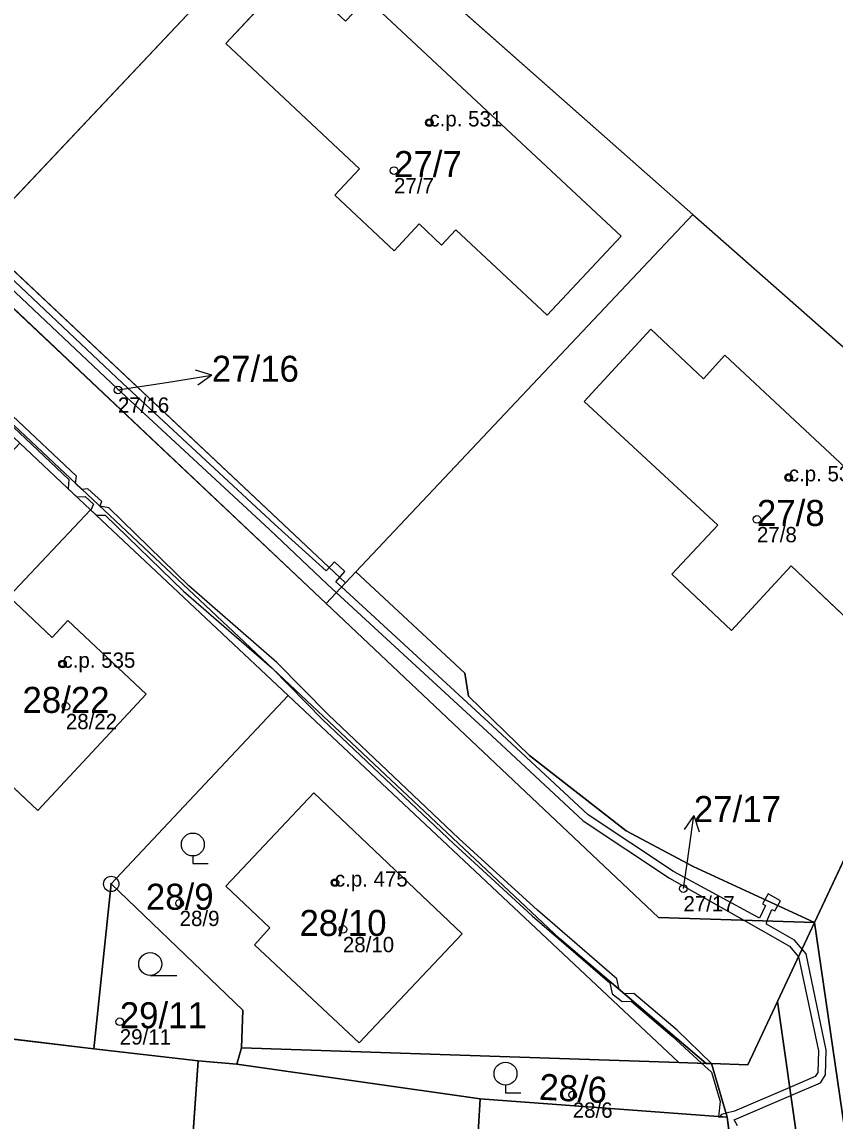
# Model space of a CAD drawing. Extents: x -603967 to -594699, y -1179315 to -1165625.
# Drawn here: x -597261.9 to -597208.8, y -1172594.2 to -1172522.4 of the extents above; entities that cross this region are included whole.
import ezdxf

# ---------------------------------------------------------------- set-up
doc = ezdxf.new("R2010")
doc.units = 0
for name, color, linetype in [('Definiční body', 7, 'Continuous'), ('Hranice parcel', 7, 'Continuous'), ('Parcelní čísla', 7, 'Continuous'), ('Polygon budovy', 7, 'Continuous'), ('Polygon parcely', 7, 'Continuous'), ('Pop  PČ popisy', 7, 'Continuous'), ('Vnitřní kresba', 7, 'Continuous'), ('Věcná břemena k části', 7, 'Continuous'), ('Značky bodu BP', 7, 'Continuous'), ('Značky budov', 7, 'Continuous'), ('Značky kultur', 7, 'Continuous')]:
    doc.layers.add(name, color=color, linetype=linetype)

msp = doc.modelspace()

# ---------------------------------------------------------------- linework, layer by layer
at = {"layer": 'Definiční body'}
for centre in [(-597235.25, -1172528.94994), (-597237.56, -1172532.07994), (-597255.59, -1172546.40994), (-597211.78, -1172552.12994), (-597213.86, -1172554.86994), (-597259.21, -1172564.30994), (-597258.99, -1172567.07994), (-597241.42, -1172578.59994), (-597218.66, -1172578.97994), (-597251.56, -1172579.93994), (-597240.9, -1172581.64994), (-597255.47, -1172587.67994), (-597225.89, -1172592.45994)]:
    msp.add_circle(centre, 0.25, dxfattribs=at)
at = {"layer": 'Hranice parcel'}
for p, q in [((-597242.77, -1172513.09), (-597264.76, -1172536.41)), ((-597242.77, -1172513.09), (-597218.04, -1172534.94)), ((-597218.04, -1172534.94), (-597240.05, -1172558.29)), ((-597218.04, -1172534.94), (-597197.09, -1172553.45)), ((-597264.76, -1172536.41), (-597240.72, -1172559)), ((-597265.99, -1172537.72), (-597242, -1172560.36)), ((-597197.09, -1172553.45), (-597210.1, -1172581.2)), ((-597240.72, -1172559), (-597240.05, -1172558.29)), ((-597242, -1172560.36), (-597240.72, -1172559)), ((-597244.48, -1172566.36), (-597256.03, -1172578.68)), ((-597218.97, -1172590.34), (-597244.48, -1172566.36)), ((-597257.17, -1172589.44), (-597256.03, -1172578.68)), ((-597212.52, -1172586.36), (-597210.1, -1172581.2)), ((-597206.62, -1172605.09), (-597210.1, -1172581.2)), ((-597212.52, -1172586.36), (-597214.45, -1172590.49)), ((-597200.46, -1172670.98), (-597212.52, -1172586.36)), ((-597257.17, -1172589.44), (-597265.61, -1172588.44)), ((-597250.35, -1172590.24), (-597257.17, -1172589.44)), ((-597247.51, -1172589.39), (-597247.83, -1172590.44)), ((-597218.97, -1172590.34), (-597247.51, -1172589.39)), ((-597251.5, -1172606.73), (-597250.35, -1172590.24)), ((-597247.83, -1172590.44), (-597250.35, -1172590.24)), ((-597247.83, -1172590.44), (-597231.93, -1172592.72)), ((-597218.97, -1172590.34), (-597217.17, -1172590.4)), ((-597217.17, -1172590.4), (-597216.82, -1172590.41)), ((-597214.45, -1172590.49), (-597216.82, -1172590.41)), ((-597216.82, -1172590.41), (-597215.81, -1172593.92)), ((-597215.81, -1172593.92), (-597231.93, -1172592.72)), ((-597212.67, -1172616.94), (-597215.81, -1172593.92))]:
    msp.add_line(p, q, dxfattribs=at)
for points in [[(-597217.17, -1172590.4), (-597226.76, -1172582.24), (-597272.66, -1172539.07), (-597331.22, -1172484)], [(-597262, -1172549.89), (-597257.38, -1172554.24), (-597244.48, -1172566.36)], [(-597240.05, -1172558.29), (-597232.94, -1172564.92), (-597232.69, -1172566.42), (-597228.72, -1172570.29), (-597222.41, -1172575.2), (-597218.02, -1172577.53), (-597210.1, -1172581.2)], [(-597242, -1172560.36), (-597220.28, -1172580.86), (-597210.1, -1172581.2)], [(-597242.8, -1172572.72), (-597233.1, -1172581.93), (-597239.84, -1172589.06), (-597246.68, -1172582.65), (-597245.66, -1172581.55), (-597248.54, -1172578.82), (-597242.8, -1172572.72)], [(-597256.03, -1172578.68), (-597247.44, -1172586.92), (-597247.51, -1172589.39)], [(-597231.93, -1172592.72), (-597232.16, -1172596.37), (-597233.65, -1172619.93)]]:
    msp.add_lwpolyline(points, dxfattribs=at)
at = {"layer": 'Polygon budovy'}
for points in [[(-597244.17, -1172519.1), (-597248.54, -1172523.78), (-597239.82, -1172531.97), (-597241.43, -1172533.68), (-597237.56, -1172537.33), (-597235.92, -1172535.57), (-597234.46, -1172536.95), (-597233.52, -1172535.95), (-597227.55, -1172541.53), (-597222.73, -1172536.37), (-597239.33, -1172520.84), (-597240.73, -1172522.32)], [(-597220.78, -1172542.45), (-597225.15, -1172547.16), (-597216.41, -1172555.25), (-597219.42, -1172558.44), (-597215.53, -1172562.12), (-597211.62, -1172557.91), (-597204.51, -1172564.65), (-597201.22, -1172557.91), (-597215.95, -1172544.14), (-597217.34, -1172545.68)], [(-597277.53, -1172566.42), (-597273.21, -1172570.48), (-597266.5, -1172563.37), (-597263.37, -1172566.3), (-597265.96, -1172569.05), (-597260.83, -1172573.88), (-597253.74, -1172566.29), (-597258.87, -1172561.48), (-597259.89, -1172562.57), (-597262.71, -1172559.91), (-597257.38, -1172554.24), (-597262, -1172549.89), (-597273.72, -1172562.36)], [(-597248.54, -1172578.82), (-597245.66, -1172581.55), (-597246.68, -1172582.65), (-597239.84, -1172589.06), (-597233.1, -1172581.93), (-597242.8, -1172572.72)]]:
    msp.add_lwpolyline(points, close=True, dxfattribs=at)
at = {"layer": 'Polygon parcely'}
for points in [[(-597230.58, -1172397.86), (-597225.66, -1172519.43), (-597370.04, -1172389.55), (-597371.62, -1172396.88), (-597322.85, -1172441.5), (-597295.24, -1172466.75), (-597267.51, -1172491.25), (-597242.77, -1172513.09), (-597218.04, -1172534.94), (-597197.09, -1172553.45), (-597129.63, -1172592.38), (-597127.98, -1172593.36), (-597111.9, -1172603.92), (-597081.9, -1172619.48), (-597063.74, -1172628.93), (-597028.61, -1172647.14), (-597018, -1172652.66), (-597016.16, -1172524.9), (-597116.51, -1172532.05), (-597117.85, -1172513.57), (-597182.62, -1172520.24), (-597187.57, -1172402.48), (-597194.03, -1172394.46), (-597229.74, -1172397.83)], [(-597327.23, -1172482.83), (-597329.2, -1172484.89), (-597330.78, -1172483.53), (-597331.22, -1172484), (-597272.66, -1172539.07), (-597226.76, -1172582.24), (-597217.17, -1172590.4), (-597216.82, -1172590.41), (-597214.45, -1172590.49), (-597212.52, -1172586.36), (-597210.1, -1172581.2), (-597220.28, -1172580.86), (-597242, -1172560.36), (-597265.99, -1172537.72), (-597289.98, -1172515.09), (-597314.07, -1172492.36), (-597314.89, -1172493.47)], [(-597262, -1172549.89), (-597257.38, -1172554.24), (-597244.48, -1172566.36), (-597218.97, -1172590.34), (-597217.17, -1172590.4), (-597226.76, -1172582.24), (-597272.66, -1172539.07), (-597331.22, -1172484), (-597331.65, -1172484.41), (-597305.83, -1172508.69), (-597295.83, -1172518.1), (-597291.22, -1172522.43), (-597286.6, -1172526.77), (-597276.61, -1172536.16), (-597266.62, -1172545.54)], [(-597264.76, -1172536.41), (-597242.77, -1172513.09), (-597267.51, -1172491.25), (-597288.81, -1172513.85)], [(-597240.05, -1172558.29), (-597218.04, -1172534.94), (-597242.77, -1172513.09), (-597264.76, -1172536.41), (-597240.72, -1172559)], [(-597218.04, -1172534.94), (-597240.05, -1172558.29), (-597232.94, -1172564.92), (-597232.69, -1172566.42), (-597228.72, -1172570.29), (-597222.41, -1172575.2), (-597218.02, -1172577.53), (-597210.1, -1172581.2), (-597197.09, -1172553.45)], [(-597242, -1172560.36), (-597240.72, -1172559), (-597264.76, -1172536.41), (-597265.99, -1172537.72)], [(-597256.03, -1172578.68), (-597244.48, -1172566.36), (-597257.38, -1172554.24), (-597262, -1172549.89), (-597273.72, -1172562.36), (-597277.53, -1172566.42), (-597283.55, -1172572.81), (-597267.25, -1172588.25), (-597265.61, -1172588.44), (-597257.17, -1172589.44)], [(-597206.62, -1172605.09), (-597130.13, -1172593.91), (-597129.63, -1172592.38), (-597197.09, -1172553.45), (-597210.1, -1172581.2)], [(-597210.1, -1172581.2), (-597218.02, -1172577.53), (-597222.41, -1172575.2), (-597228.72, -1172570.29), (-597232.69, -1172566.42), (-597232.94, -1172564.92), (-597240.05, -1172558.29), (-597240.72, -1172559), (-597242, -1172560.36), (-597220.28, -1172580.86)], [(-597244.48, -1172566.36), (-597256.03, -1172578.68), (-597247.44, -1172586.92), (-597247.51, -1172589.39), (-597218.97, -1172590.34)], [(-597242.8, -1172572.72), (-597233.1, -1172581.93), (-597239.84, -1172589.06), (-597246.68, -1172582.65), (-597245.66, -1172581.55), (-597248.54, -1172578.82)], [(-597242.8, -1172572.72), (-597248.54, -1172578.82), (-597245.66, -1172581.55), (-597246.68, -1172582.65), (-597239.84, -1172589.06), (-597233.1, -1172581.93)], [(-597247.51, -1172589.39), (-597247.44, -1172586.92), (-597256.03, -1172578.68), (-597257.17, -1172589.44), (-597250.35, -1172590.24), (-597247.83, -1172590.44)], [(-597206.62, -1172605.09), (-597210.1, -1172581.2), (-597212.52, -1172586.36), (-597200.46, -1172670.98), (-597197.06, -1172670.81), (-597200.14, -1172649.62), (-597203.38, -1172627.35)], [(-597200.39, -1172674.62), (-597200.46, -1172670.98), (-597212.52, -1172586.36), (-597214.45, -1172590.49), (-597216.82, -1172590.41), (-597215.81, -1172593.92), (-597212.67, -1172616.94), (-597209.4, -1172640.92), (-597205.28, -1172671.19), (-597204.91, -1172674.99), (-597204.13, -1172680.6), (-597201.71, -1172697.9), (-597199.52, -1172712.29), (-597197.72, -1172725.66), (-597195.27, -1172739.28), (-597192.33, -1172756.74), (-597187.54, -1172781.71), (-597186.69, -1172787.77), (-597184.18, -1172779.24), (-597184.59, -1172776.79)], [(-597250.35, -1172590.24), (-597257.17, -1172589.44), (-597265.61, -1172588.44), (-597266.7, -1172605.49), (-597251.5, -1172606.73)], [(-597247.83, -1172590.44), (-597231.93, -1172592.72), (-597215.81, -1172593.92), (-597216.82, -1172590.41), (-597217.17, -1172590.4), (-597218.97, -1172590.34), (-597247.51, -1172589.39)], [(-597234.54, -1172634), (-597233.65, -1172619.93), (-597232.16, -1172596.37), (-597231.93, -1172592.72), (-597247.83, -1172590.44), (-597250.35, -1172590.24), (-597251.5, -1172606.73), (-597253.76, -1172639.07), (-597249.06, -1172639.54), (-597244.8, -1172639.84), (-597244.33, -1172633.31)], [(-597231.93, -1172592.72), (-597232.16, -1172596.37), (-597233.65, -1172619.93), (-597227.14, -1172619.03), (-597217.22, -1172617.58), (-597212.67, -1172616.94), (-597215.81, -1172593.92)]]:
    msp.add_lwpolyline(points, close=True, dxfattribs=at)
at = {"layer": 'Pop  PČ popisy'}
for p, q in [((-597249.456, -1172545.451), (-597250.523, -1172545.113)), ((-597255.59, -1172546.41), (-597252.42, -1172545.92)), ((-597252.42, -1172545.92), (-597249.456, -1172545.451)), ((-597249.456, -1172545.451), (-597250.367, -1172546.102)), ((-597217.982, -1172574.208), (-597218.618, -1172575.13)), ((-597218.4, -1172577.18), (-597217.982, -1172574.208)), ((-597217.982, -1172574.208), (-597217.626, -1172575.27)), ((-597218.66, -1172578.98), (-597218.4, -1172577.18))]:
    msp.add_line(p, q, dxfattribs=at)
at = {"layer": 'Vnitřní kresba'}
for p, q in [((-597244.17, -1172519.1), (-597248.54, -1172523.78)), ((-597222.73, -1172536.37), (-597239.33, -1172520.84)), ((-597248.54, -1172523.78), (-597239.82, -1172531.97)), ((-597239.82, -1172531.97), (-597241.43, -1172533.68)), ((-597241.43, -1172533.68), (-597237.56, -1172537.33)), ((-597237.56, -1172537.33), (-597235.92, -1172535.57)), ((-597235.92, -1172535.57), (-597234.46, -1172536.95)), ((-597234.46, -1172536.95), (-597233.52, -1172535.95)), ((-597233.52, -1172535.95), (-597227.55, -1172541.53)), ((-597227.55, -1172541.53), (-597222.73, -1172536.37)), ((-597225.15, -1172547.16), (-597220.78, -1172542.45)), ((-597220.78, -1172542.45), (-597217.34, -1172545.68)), ((-597217.34, -1172545.68), (-597215.95, -1172544.14)), ((-597215.95, -1172544.14), (-597201.22, -1172557.91)), ((-597216.41, -1172555.25), (-597225.15, -1172547.16)), ((-597262.71, -1172559.91), (-597257.38, -1172554.24)), ((-597219.42, -1172558.44), (-597216.41, -1172555.25)), ((-597211.62, -1172557.91), (-597215.53, -1172562.12)), ((-597204.51, -1172564.65), (-597211.62, -1172557.91)), ((-597215.53, -1172562.12), (-597219.42, -1172558.44)), ((-597259.89, -1172562.57), (-597262.71, -1172559.91)), ((-597258.87, -1172561.48), (-597259.89, -1172562.57)), ((-597253.74, -1172566.29), (-597258.87, -1172561.48)), ((-597260.83, -1172573.88), (-597253.74, -1172566.29)), ((-597265.96, -1172569.05), (-597260.83, -1172573.88))]:
    msp.add_line(p, q, dxfattribs=at)
at = {"layer": 'Věcná břemena k části'}
for points in [[(-597265.42, -1172537.11), (-597255.63, -1172546.32), (-597245.7, -1172555.53), (-597241.92, -1172559.1), (-597241.33, -1172559.65), (-597231.47, -1172568.72), (-597225.2, -1172574.56), (-597219.56, -1172578.29), (-597214.72, -1172581.05), (-597213.61, -1172581.68), (-597211.73, -1172582.74), (-597211.15, -1172583.43), (-597210.91, -1172582.93), (-597211.41, -1172582.34), (-597213.24, -1172581.31), (-597213.22, -1172581.1), (-597212.88, -1172580.34), (-597212.7, -1172580.44), (-597212.33, -1172579.79), (-597213.13, -1172579.33), (-597213.5, -1172579.98), (-597213.31, -1172580.09), (-597213.69, -1172580.92), (-597219.3, -1172577.87), (-597224.88, -1172574.16), (-597231.13, -1172568.36), (-597240.99, -1172559.28), (-597241.36, -1172558.94), (-597240.77, -1172558.27), (-597241.44, -1172557.64), (-597241.99, -1172558.23), (-597245.36, -1172555.17), (-597255.29, -1172545.96), (-597265.07, -1172536.75)], [(-597266.07, -1172545.41), (-597258.8, -1172552.25), (-597258.84, -1172552.86), (-597258.28, -1172553.39), (-597257.73, -1172553.36), (-597257.19, -1172553.87), (-597257.35, -1172554.26), (-597256.99, -1172554.6), (-597256.43, -1172554.58), (-597251.3, -1172559.56), (-597245.55, -1172564.56), (-597242.19, -1172567.99), (-597233.66, -1172576.06), (-597228.53, -1172580.77), (-597223.47, -1172585.13), (-597223.32, -1172585.85), (-597222.67, -1172586.35), (-597222.07, -1172586.34), (-597219.4, -1172588.62), (-597217.47, -1172590.39), (-597216.82, -1172590.41), (-597219.06, -1172588.24), (-597221.91, -1172585.84), (-597222.52, -1172585.85), (-597222.85, -1172585.57), (-597223.01, -1172584.87), (-597228.19, -1172580.39), (-597233.32, -1172575.7), (-597241.85, -1172567.63), (-597245.22, -1172564.22), (-597250.96, -1172559.2), (-597256.19, -1172554.12), (-597256.77, -1172554.01), (-597256.65, -1172553.69), (-597257.55, -1172552.86), (-597257.95, -1172552.91), (-597258.36, -1172552.52), (-597258.3, -1172552.05), (-597265.91, -1172544.87)], [(-597215.12, -1172594.47), (-597215.35, -1172594.08), (-597211.65, -1172592.49), (-597209.72, -1172591.66), (-597209.39, -1172591.15), (-597209.35, -1172589.53), (-597210.65, -1172583.25), (-597210.91, -1172582.93), (-597211.15, -1172583.43), (-597209.85, -1172589.57), (-597209.89, -1172590.99), (-597210.06, -1172591.26), (-597211.72, -1172591.97), (-597215.32, -1172593.52), (-597215.88, -1172593.66), (-597215.81, -1172593.92), (-597215.15, -1172598.77)]]:
    msp.add_lwpolyline(points, dxfattribs=at)
for points in [[(-597215.81, -1172593.92), (-597216.82, -1172590.41), (-597217.47, -1172590.39), (-597216.83, -1172590.98), (-597216.26, -1172592.89), (-597216.38, -1172593.88)], [(-597216.31, -1172593.88), (-597215.81, -1172593.92), (-597215.88, -1172593.66), (-597216.18, -1172593.73)]]:
    msp.add_lwpolyline(points, close=True, dxfattribs=at)
at = {"layer": 'Značky bodu BP'}
for radius in [0.5, 0.0303]:
    msp.add_circle((-597256.03, -1172578.67988), radius, dxfattribs=at)
at = {"layer": 'Značky budov'}
for centre in [(-597235.2568, -1172528.94916), (-597211.7868, -1172552.12916), (-597259.2168, -1172564.30916), (-597241.4268, -1172578.59916)]:
    msp.add_circle(centre, 0.175, dxfattribs=at)
at = {"layer": 'Značky kultur'}
for p, q in [((-597250.7, -1172576.852), (-597250.7, -1172577.35)), ((-597250.7, -1172577.35), (-597249.699, -1172577.35)), ((-597253.483, -1172584.66), (-597251.733, -1172584.66)), ((-597230.28, -1172591.822), (-597230.28, -1172592.32)), ((-597230.28, -1172592.32), (-597229.279, -1172592.32))]:
    msp.add_line(p, q, dxfattribs=at)
for centre in [(-597250.69929, -1172576.1009), (-597253.48286, -1172583.90981), (-597230.27929, -1172591.0709)]:
    msp.add_circle(centre, 0.75, dxfattribs=at)

# ---------------------------------------------------------------- texts
at = {"layer": 'Definiční body'}
for s, p in [('c.p. 531', (-597235.25, -1172529.2)), ('27/7', (-597237.56, -1172533.569)), ('27/16', (-597255.59, -1172547.899)), ('c.p. 530', (-597211.78, -1172552.38)), ('27/8', (-597213.86, -1172556.359)), ('c.p. 535', (-597259.21, -1172564.56)), ('28/22', (-597258.99, -1172568.569)), ('c.p. 475', (-597241.42, -1172578.85)), ('27/17', (-597218.66, -1172580.469)), ('28/9', (-597251.56, -1172581.429)), ('28/10', (-597240.9, -1172583.139)), ('29/11', (-597255.47, -1172589.169)), ('28/6', (-597225.89, -1172593.949))]:
    msp.add_text(s, height=0.999996, dxfattribs=at).set_placement(p)
at = {"layer": 'Parcelní čísla'}
for s, p in [('27/7', (-597237.56, -1172532.505)), ('27/16', (-597249.46, -1172545.875)), ('27/8', (-597213.86, -1172555.295)), ('28/22', (-597261.826, -1172567.505)), ('27/17', (-597217.98, -1172574.635)), ('28/9', (-597253.765, -1172580.365)), ('28/10', (-597243.736, -1172582.075)), ('29/11', (-597255.47, -1172588.105))]:
    msp.add_text(s, height=1.699998, dxfattribs=at).set_placement(p)
msp.add_text('28/6', height=1.699998, rotation=357, dxfattribs=at).set_placement((-597228.115, -1172592.768))

doc.saveas('drawing.dxf')
